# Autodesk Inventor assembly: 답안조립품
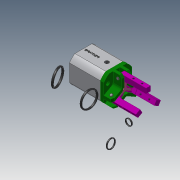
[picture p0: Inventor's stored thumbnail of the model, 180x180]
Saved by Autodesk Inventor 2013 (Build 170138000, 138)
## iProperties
Created: 2020-02
Part Number: 답안조립품
Document SubType Name: Assembly
Designer: CADCOM
Author: CADCOM
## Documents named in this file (13)
- C:\Users\CADCOM\Desktop\700206V1010\답안조립품.iam
- C:\Users\CADCOM\Desktop\700206V1010\본체.ipt
- C:\Users\CADCOM\Desktop\700206V1010\E링.ipt
- C:\Users\CADCOM\Desktop\700206V1010\O-RING 12x16.ipt
- C:\Users\CADCOM\Desktop\700206V1010\O-RING 18x22.ipt
- C:\Users\CADCOM\Desktop\700206V1010\O-RING 34x40.ipt
- C:\Users\CADCOM\Desktop\700206V1010\로드.ipt
- C:\Users\CADCOM\Desktop\700206V1010\본체헤드.ipt
- C:\Users\CADCOM\Desktop\700206V1010\볼트 M4.ipt
- C:\Users\CADCOM\Desktop\700206V1010\피스톤.ipt
- C:\Users\CADCOM\Desktop\700206V1010\핀 A.ipt
- C:\Users\CADCOM\Desktop\700206V1010\핀 B.ipt
- C:\Users\CADCOM\Desktop\700206V1010\핑거.ipt
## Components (20 placed, 8 different names)
1. E링:1
2. O-RING 12x16:1
3. O-RING 18x22:1
4. O-RING 34x40:1
5. 피스톤:1
6. 핀 A:1
7. 핀 B:1 — 플러쉬:1
8. 핑거:1 — 플러쉬:3
9. 핑거:2 — 플러쉬:2
10. 핑거:3 — 플러쉬:1
11. E링:2
12. E링:3
13. 핀 A:2
14. 핀 A:3
15. E링:4
16. E링:5
17. E링:6
18. 핀 B:2 — 플러쉬:2
19. 핀 B:3 — 플러쉬:3
20. O-RING 34x40:2
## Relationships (3: Flush 3)
- 플러쉬:1 [Flush]: 핀 B:1 ↔ 핑거:3
- 플러쉬:2 [Flush]: 핑거:2 ↔ 핀 B:2
- 플러쉬:3 [Flush]: 핑거:1 ↔ 핀 B:3
